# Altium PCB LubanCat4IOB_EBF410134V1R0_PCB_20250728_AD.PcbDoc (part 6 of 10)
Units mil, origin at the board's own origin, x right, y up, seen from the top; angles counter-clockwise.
Board outline 5236.21 x 4055.11 mil, 6 copper layers (TOP, GND02, ART03, PWR04, GND05, BOTTOM), stack 47.2 mil thick; 614 components, 490 nets, 2311 pads, 1916 vias.
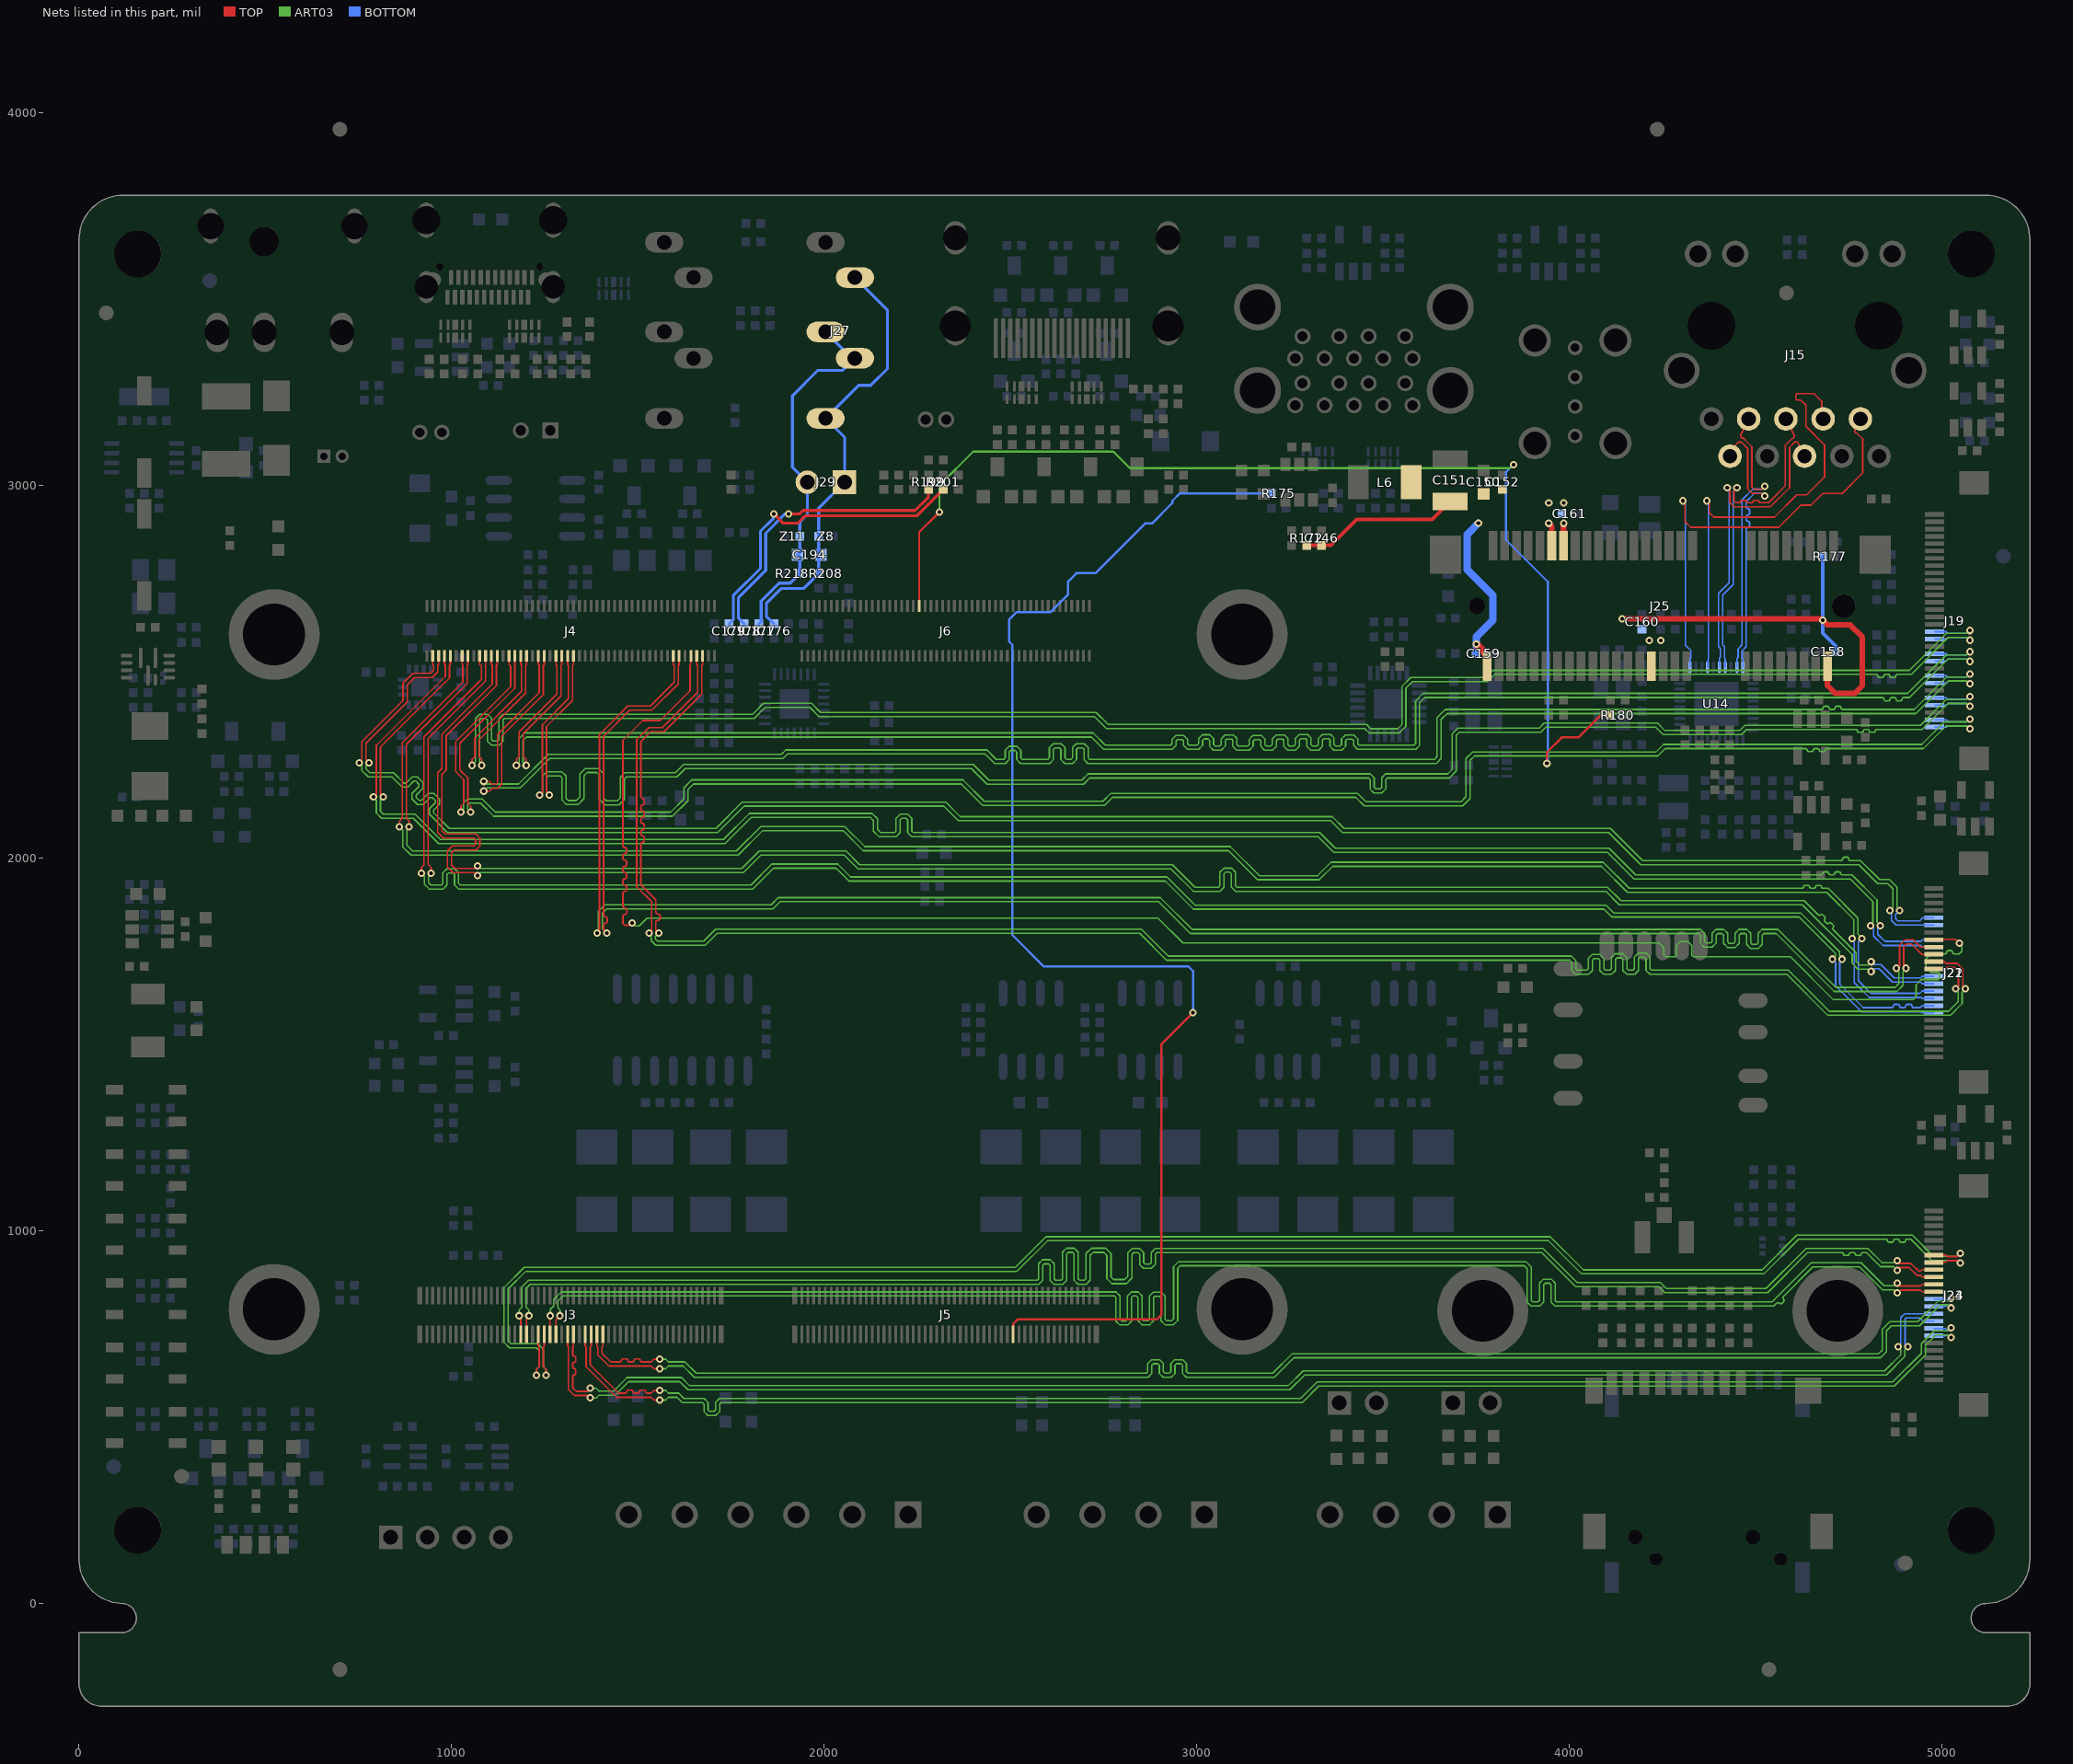
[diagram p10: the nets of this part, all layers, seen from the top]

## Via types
v1: diameter 20, hole 10, TOP to BOTTOM, 1912 vias
v2: diameter 40/50/50/50/50/40 (per signal layer), hole 0, TOP to BOTTOM, 4 vias

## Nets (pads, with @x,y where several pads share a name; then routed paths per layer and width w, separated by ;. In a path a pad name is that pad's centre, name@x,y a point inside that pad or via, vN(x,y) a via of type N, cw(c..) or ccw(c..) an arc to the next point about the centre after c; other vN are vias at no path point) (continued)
MDIN2_PHY: J15.6 U14.7 | length 907.5
  TOP w4.2: v1(4450,2994.37) 4441.85,2986.22 4441.85,2959.88 4447.56,2954.17 4456.77,2954.17 ccw(c4456.77,2956.61) 4459.2,2956.61 cw(c4463.36,2956.61) 4463.36,2960.77 4471.84,2960.77 cw(c4471.84,2956.61) 4476,2956.61 ccw(c4478.44,2956.61) 4478.44,2954.17 4490.36,2954.17 ccw(c4490.36,2956.61) 4492.8,2956.61 cw(c4496.74,2956.61) 4496.74,2960.55 4505.65,2960.55 cw(c4505.65,2956.61) 4509.6,2956.61 ccw(c4512.03,2956.61) 4512.03,2954.17 4534.8,2954.17 4580,2999.37 4580,3107.99 4597.73,3125.72 4602.08,3127.9 4604.09,3133.92 J15.6@4581.49,3179.13
  BOTTOM w4.2: U14.7@4418.62,2512.8 4418.62,2535.75 4416.47,2537.9 4416.47,2567.53 4411.86,2572.14 4411.86,2706.22 4440.2,2734.57 4440.2,2984.57 v1(4450,2994.37)
MDIN3_PHY: J15.9 U14.10 | length 769.7
  TOP w4.2: J15.9@4431.49,3079.13 4446.62,3109.39 4454.06,3116.83 4461.86,3116.83 4461.98,3116.77 4478.8,3099.95 4478.8,2992.21 4491.92,2979.09 4517.7,2979.09 v1(4524.52,2972.27)
  BOTTOM w4.2: U14.10@4465.87,2512.8 4465.87,2536 4464.18,2537.69 4464.18,2557.18 4475,2568 4475,2883.19 cw(c4479.5,2883.19) 4479.5,2887.69 ccw(c4479.5,2892.19) 4484,2892.19 4484,2899.99 ccw(c4479.5,2899.99) 4479.5,2904.49 cw(c4479.5,2908.99) 4475,2908.99 4475,2916.79 cw(c4479.5,2916.79) 4479.5,2921.29 ccw(c4479.5,2925.79) 4484,2925.79 4484,2933.59 ccw(c4479.5,2933.59) 4479.5,2938.09 cw(c4479.5,2942.59) 4475,2942.59 4475,2957.16 4497.41,2979.57 4516.39,2979.57 4523.69,2972.27 v1(4524.52,2972.27)
MDIP0_PHY: J15.2 U14.1 | length 1217
  TOP w4.2: v1(4304.5,2959.37) 4310.35,2953.52 4310.35,2903.71 4325.89,2888.17 4562.14,2888.17 4621.64,2947.67 4648.49,2947.67 4680.18,2979.36 4732.47,2979.36 4787.59,3034.48 4787.59,3125.41 4774.32,3138.68 4773.04,3139.97 4771.41,3140.78 4769.65,3141.66 4767.89,3142.54 4766.02,3148.17 J15.2@4781.49,3179.13
  BOTTOM w4.2: v1(4304.5,2959.37) 4305.04,2959.37 4311.9,2952.51 4311.9,2571.91 4326.33,2557.48 4326.33,2538.2 4324.13,2536 U14.1@4324.13,2512.8
MDIP1_PHY: J15.4 U14.4 | length 1230
  TOP w4.2: v1(4368.63,2959.37) 4376.17,2951.83 4376.17,2927.36 4387.96,2915.57 4550.79,2915.57 4610.29,2975.07 4637.14,2975.07 4685,3022.93 4685,3109.37 4635,3159.37 4635,3215.9 4620.94,3229.96 4610.9,3229.96 4607.93,3232.93 4607.93,3243.19 4612.13,3247.39 4656.7,3247.39 4677.64,3226.45 4677.64,3182.98 J15.4@4681.49,3179.13
  BOTTOM w4.2: v1(4368.63,2959.37) 4373.66,2954.34 4373.66,2954.24 4373.26,2953.84 4373.26,2531.39 4371.38,2529.52 U14.4@4371.38,2512.8
MDIP2_PHY: J15.5 U14.6 | length 905.6
  TOP w4.2: v1(4424,2994.37) 4430.65,2987.72 4430.65,2955.24 4442.93,2942.97 4539.44,2942.97 4591.2,2994.73 4591.2,3103.35 4604.36,3116.51 4608.05,3118.36 4612.64,3116.83 J15.5@4631.49,3079.13
  BOTTOM w4.2: U14.6@4402.87,2512.8 4402.87,2537.24 4405.27,2539.64 4405.27,2562.89 4400.66,2567.5 4400.66,2710.86 4429,2739.21 4429,2989.37 v1(4424,2994.37)
MDIP3_PHY: J15.8 U14.9 | length 772.6
  TOP w4.2: J15.8@4481.49,3179.13 4459.66,3135.47 4461.67,3129.45 4463.09,3128.03 4464.97,3128.03 4467.26,3126.66 4471.14,3124.72 4471.77,3122.82 4490,3104.59 4490,2996.85 4496.56,2990.29 4516.54,2990.29 v1(4524.52,2998.27)
  BOTTOM w4.2: U14.9@4450.12,2512.8 4450.12,2536 4452.98,2538.86 4452.98,2561.82 4463.8,2572.64 4463.8,2961.8 4492.77,2990.77 4517.02,2990.77 v1(4524.52,2998.27)
MIC1_L: C176.2 C194.1 J27.2 J27.4 J29.1 R208.2 Z8.2 | length 1210.5
  BOTTOM w8: C176.2@1865,2629.05 1845,2649.05 1845,2684.37 1885,2724.37 1945.32,2724.37 R208.2@1985.32,2764.37 1985.32,2808.19 C194.1@1991.5,2814.37 1985.32,2820.55 Z8.2@1985.32,2864.37 1985.32,2939.69 J29.1@2055,3009.37 2055,3129.35 J27.4@2003.77,3180.57 2092.57,3269.37 2125,3269.37 2170,3314.37 2170,3471.03 J27.2@2082.51,3558.52
MIC1_R: C177.2 C194.2 J27.3 J27.5 J29.2 R218.1 Z11.2 | length 1022.4
  BOTTOM w8: C177.2@1825,2629.05 1831,2635.05 1831,2690.17 1879.2,2738.37 1908.68,2738.37 R218.1@1934.68,2764.37 1934.68,2808.19 C194.2@1928.5,2814.37 1934.68,2820.55 Z11.2@1934.68,2864.37 1934.68,2903.05 1955,2923.37 J29.2@1955,3009.37 1915,3049.37 1915,3241.37 1983,3309.37 2049.89,3309.37 J27.3@2082.51,3341.99 2074.63,3341.99 J27.5@2003.77,3412.85
MIC2_L: C178.2 R199.2 | length 777.2
  TOP w8: v1(1904.37,2924.37) 1934.2,2924.37 1943.2,2933.37 2243.88,2933.37 2280,2969.49 R199.2@2280,2989.69
  BOTTOM w8: C178.2@1785,2629.05 1770,2644.05 1770,2699.57 1843,2772.57 1843,2872.37 1895,2924.37 v1(1904.37,2924.37)
MIC2_R: C179.2 R201.2 | length 847.8
  TOP w8: v1(1865,2924.37) 1890,2899.37 1929,2899.37 1949,2919.37 2249.68,2919.37 R201.2@2320,2989.69
  BOTTOM w8: C179.2@1745,2629.05 1756,2640.05 1756,2705.37 1829,2778.37 1829,2878.17 1865,2914.17 v1(1865,2924.37)
MINIPCIE_3V3: C146.1 C150.1 C151.1 C152.1 C158.1 C159.1 C160.1 C161.1 J25.2 J25.24 J25.39 J25.41 J25.52 L6.2 R172.1 R177.1 | length 2267.6
  TOP w10: R172.1@3295,2839.69 C146.1@3335,2839.69 3360.32,2839.69 3430,2909.37 3632.09,2909.37 C151.1@3680,2957.28
  TOP w15: v1(3945,2898.95) 3952.9,2891.05 J25.41@3952.9,2838.58 ; J25.39@3984.39,2838.58 3984.39,2898.34 v1(3985,2898.95) ; v1(4142,2642.37) 4677,2642.37 v1(4680,2639.37) 4693,2626.37 4754,2626.37 4787,2593.37 4787,2463.58 4765.79,2442.37 4714.27,2442.37 4693.06,2463.58 J25.2@4693.06,2515.74
  TOP w20: v1(3750,2574.37) 3779.67,2544.7 J25.52@3779.67,2515.74
  BOTTOM w10: v1(4680,2639.37) v1@4680.32,2639.69 ; R177.1@4680.32,2809.37 v1@4680.32,2639.69 ; C158.1@4714.68,2554.37 4714.68,2569.69 4680.32,2604.05 v1@4680.32,2639.69
  BOTTOM w20: v1(3750,2574.37) v1@3750.32,2574.05 ; C159.1@3750.32,2549.37 v1@3750.32,2574.05 ; v1(3756,2899.37) 3725.6,2868.97 3725.6,2774.57 3795,2705.17 3795,2639.37 3750.32,2594.69 v1@3750.32,2574.05
  other v1: 4246,2584.37 4215,2584.59 3945,2953.95 3985,2953.95
MINIPCIE_NWDISABLE: J6.42 R180.2 | length 3046
  TOP w6: J6.42@2255.11,2677.37 2255.11,2875.29 v1(2309.2,2929.37) ; v1(3940,2254.37) 3940,2284.37 3980,2324.37 4025,2324.37 4085,2384.37 R180.2@4110.32,2384.37
  ART03 w5.5: v1(2309.2,2929.37) 2309.2,3000.56 2400,3091.37 2776,3091.37 2820.6,3046.77 3840.4,3046.77 v1(3850,3056.37)
  BOTTOM w6: v1(3850,3056.37) 3830,3036.37 3830,2854.37 3942.4,2741.97 3942.4,2256.77 v1(3940,2254.37)
MINIPCIE_PWR_EN: J5.74 R175.1 | length 3637.6
  TOP w6: J5.74@2507.08,722.26 2507.08,750.37 2519.08,762.37 2893,762.37 2905,774.37 2905,1500.37 v1(2990,1585.37)
  BOTTOM w6: v1(2990,1585.37) 2990,1697.37 2978,1709.37 2590,1709.37 2505,1794.37 2505,2573 2496,2582 2496,2640 2516,2660 2607,2660 2655,2708 2655,2743 2677,2765 2728,2765 2862.37,2899.37 2881,2899.37 2935,2953.37 2935,2959.37 2955,2979.37 R175.1@3200.32,2979.37
MIPI_CSI0_RX_CLK0N: J3.52 J23.10 | length 3995.8
  TOP w4.2: J3.52@1327.26,722.26 1327.26,690.84 1324.98,688.57 1324.98,668 ccw(c1328.99,668) 1328.99,663.99 cw(c1328.99,659.98) 1333,659.98 1333,651.2 cw(c1328.99,651.2) 1328.99,647.19 ccw(c1328.99,643.18) 1324.98,643.18 1324.98,634.4 ccw(c1328.99,634.4) 1328.99,630.39 cw(c1328.99,626.38) 1333,626.38 1333,617.6 cw(c1328.99,617.6) 1328.99,613.59 ccw(c1328.99,609.58) 1324.98,609.58 1324.98,578.77 1334.38,569.37 1364.73,569.37 1372.53,577.17 v1(1372.53,577.77)
  ART03 w4: v1(1372.53,577.77) 1388.15,577.77 1395.65,570.27 1434.9,570.27 1471,606.37 1617,606.37 1639,584.37 3245.44,584.37 3285.44,624.37 4846.44,624.37 4890,667.93 4890,681.14 v1(4882.5,688.64)
  BOTTOM w4.2: v1(4882.5,688.64) 4889.9,696.04 4889.9,767.3 4900.16,777.56 J23.10@4978.61,777.56
MIPI_CSI0_RX_CLK0P: J3.50 J23.9 | length 3998
  TOP w4.2: J3.50@1311.51,722.26 1311.51,690.84 1313.78,688.57 1313.78,574.13 1329.74,558.17 1366.13,558.17 v1(1372.53,551.77)
  ART03 w4: v1(1372.53,551.77) 1388.15,551.77 1395.65,559.27 1439.46,559.27 1475.56,595.37 1612.44,595.37 1634.44,573.37 3250,573.37 3290,613.37 4851,613.37 4901,663.37 4901,681.14 v1(4908.5,688.64)
  BOTTOM w4.2: v1(4908.5,688.64) 4901.1,696.04 4901.1,762.66 4904.8,766.36 4941.01,766.36 4949.5,757.87 J23.9@4978.61,757.87
MIPI_CSI0_RX_CLK1N: J3.36 J24.10 | length 4582.1
  TOP w4.2: J3.36@1201.27,722.26 1201.27,766.23 v1(1207.4,772.36) ; v1(4880,894.37) 4887,901.37 4912.16,901.37 4932.82,880.71 4942.42,880.71 4947.15,875.98 J24.10@4978.61,875.98
  ART03 w4: v1(1207.4,772.36) 1207.4,787.99 1199.9,795.49 1199.9,845.27 1211.06,856.42 2576.02,856.42 2586.47,866.87 2586.47,907.37 2590.47,911.37 2602.47,911.37 2606.47,907.37 2606.47,866.87 2616.91,856.42 2640.56,856.42 2651,866.87 2651,938.37 2655,942.37 2667,942.37 2671,938.37 2671,866.87 2681.44,856.42 2703.05,856.42 2714,867.37 2714,934.37 2722,942.37 2751,942.37 2759,934.37 2759,871.81 2772.44,858.37 2811,858.37 2826.45,873.82 2826.45,936.81 2831,941.37 2842.72,941.37 2846.72,937.37 2846.72,909.81 2857.16,899.37 2878.28,899.37 2888.72,909.81 2888.72,937.37 2892.72,941.37 3925.84,941.37 4017.21,850 4240.44,850 4256.07,834.37 4532.56,834.37 4639.56,941.37 4732.28,941.37 cw(c4732.28,937.87) 4735.78,937.87 ccw(c4739.28,937.87) 4739.28,934.37 4748.28,934.37 ccw(c4748.28,937.87) 4751.78,937.87 cw(c4755.28,937.87) 4755.28,941.37 4764.28,941.37 cw(c4764.28,937.87) 4767.78,937.87 ccw(c4771.28,937.87) 4771.28,934.37 4780.28,934.37 ccw(c4780.28,937.87) 4783.78,937.87 cw(c4787.28,937.87) 4787.28,941.37 4797.44,941.37 4834.94,903.87 4870.5,903.87 v1(4880,894.37)
MIPI_CSI0_RX_CLK1P: J3.34 J24.9 | length 4581.8
  TOP w4.2: v1(1181.4,772.36) 1185.52,768.23 J3.34@1185.52,722.26 ; v1(4880,920.37) 4887.8,912.57 4916.8,912.57 4937.46,891.91 4943.4,891.91 4947.15,895.67 J24.9@4978.61,895.67
  ART03 w4: v1(1181.4,772.36) 1181.4,787.99 1188.9,795.49 1188.9,849.83 1206.5,867.42 2571.47,867.42 2575.47,871.42 2575.47,911.93 2585.91,922.37 2607.02,922.37 2617.47,911.93 2617.47,871.42 2621.47,867.42 2636,867.42 2640,871.42 2640,942.93 2650.44,953.37 2671.56,953.37 2682,942.93 2682,871.42 2686,867.42 2698.5,867.42 2703,871.93 2703,938.93 2717.44,953.37 2755.56,953.37 2770,938.93 2770,876.37 2777,869.37 2806.44,869.37 2815.45,878.37 2815.45,941.37 2826.44,952.37 2847.28,952.37 2857.72,941.93 2857.72,914.37 2861.72,910.37 2873.72,910.37 2877.72,914.37 2877.72,941.93 2888.16,952.37 3930.4,952.37 4021.77,861 4245,861 4260.63,845.37 4528,845.37 4635,952.37 4802,952.37 4839.5,914.87 4874.5,914.87 v1(4880,920.37)
MIPI_CSI0_RX_D0N: J3.62 J23.12 | length 3998.5
  TOP w4.2: J3.62@1406,722.26 1406,690.84 1403.72,688.57 1403.72,671.49 1426.84,648.37 1452.07,648.37 ccw(c1452.07,652.37) 1456.07,652.37 cw(c1460.07,652.37) 1460.07,656.37 1468.87,656.37 cw(c1468.87,652.37) 1472.87,652.37 ccw(c1476.87,652.37) 1476.87,648.37 1485.67,648.37 ccw(c1485.67,652.37) 1489.67,652.37 cw(c1493.67,652.37) 1493.67,656.37 1502.47,656.37 cw(c1502.47,652.37) 1506.47,652.37 ccw(c1510.47,652.37) 1510.47,648.37 1535.95,648.37 1543.35,655.77 v1(1559,655.77)
  ART03 w4: v1(1559,655.77) 1574.63,655.77 1582.13,648.27 1626.1,648.27 1656.55,617.82 2864.61,617.82 2868.61,621.82 2868.61,643.93 2879.05,654.37 2900.17,654.37 2910.61,643.93 2910.61,621.82 2914.61,617.82 2926.61,617.82 2930.61,621.82 2930.61,643.93 2941.05,654.37 2962.17,654.37 2972.61,643.93 2972.61,621.82 2976.61,617.82 3203.89,617.82 3256.44,670.37 4830.44,670.37 4840,679.93 4840,735.93 4860.44,756.37 4935.44,756.37 4991.44,812.37 5018,812.37 v1(5025,819.37)
  BOTTOM w4.2: J23.12@4978.61,816.93 5010.03,816.93 5013.47,813.49 5019.12,813.49 v1(5025,819.37)
MIPI_CSI0_RX_D0P: J3.60 J23.11 | length 3999.2
  TOP w4.2: J3.60@1390.25,722.26 1390.25,690.84 1392.52,688.57 1392.52,666.85 1422.2,637.17 1535.95,637.17 1543.35,629.77 v1(1559,629.77)
  ART03 w4: v1(1559,629.77) 1574.63,629.77 1582.13,637.27 1621.54,637.27 1651.99,606.82 2869.17,606.82 2879.61,617.26 2879.61,639.37 2883.61,643.37 2895.61,643.37 2899.61,639.37 2899.61,617.26 2910.05,606.82 2931.17,606.82 2941.61,617.26 2941.61,639.37 2945.61,643.37 2957.61,643.37 2961.61,639.37 2961.61,617.26 2972.05,606.82 3208.45,606.82 3261,659.37 4835,659.37 4851,675.37 4851,731.37 4865,745.37 4940,745.37 4996,801.37 5017,801.37 v1(5025,793.37)
  BOTTOM w4.2: J23.11@4978.61,797.24 5010.03,797.24 5012.75,799.96 5018.41,799.96 v1(5025,793.37)
MIPI_CSI0_RX_D1N: J3.58 J23.8 | length 3994.3
  TOP w4.2: J3.58@1374.5,722.26 1374.5,690.84 1372.23,688.57 1372.23,640.14 1448,564.37 1466.3,564.37 ccw(c1466.3,568.37) 1470.3,568.37 cw(c1474.3,568.37) 1474.3,572.37 1483.1,572.37 cw(c1483.1,568.37) 1487.1,568.37 ccw(c1491.1,568.37) 1491.1,564.37 1499.9,564.37 ccw(c1499.9,568.37) 1503.9,568.37 cw(c1507.9,568.37) 1507.9,572.37 1516.7,572.37 cw(c1516.7,568.37) 1520.7,568.37 ccw(c1524.7,568.37) 1524.7,564.37 1535.95,564.37 1543.35,571.77 v1(1559,571.77)
  ART03 w4: v1(1559,571.77) 1574.63,571.77 1582.13,564.27 1609.66,564.27 1623.56,550.37 1677.87,550.37 1688.31,539.93 1688.31,519.37 1692.31,515.37 1704.31,515.37 1708.31,519.37 1708.31,539.93 1718.75,550.37 3279,550.37 3323,594.37 4868,594.37 4945,671.37 4945,697.37 4979.5,731.87 5017.5,731.87 v1(5025,739.37)
  BOTTOM w4.2: J23.8@4978.61,738.19 5010.03,738.19 5014.1,734.12 5019.75,734.12 v1(5025,739.37)
MIPI_CSI0_RX_D1P: J3.56 J23.7 | length 3994.5
  TOP w4.2: J3.56@1358.75,722.26 1358.75,690.84 1361.03,688.57 1361.03,635.5 1443.36,553.17 1535.95,553.17 1543.35,545.77 v1(1559,545.77)
  ART03 w4: v1(1559,545.77) 1574.63,545.77 1582.13,553.27 1605.1,553.27 1619,539.37 1673.31,539.37 1677.31,535.37 1677.31,514.81 1687.75,504.37 1708.87,504.37 1719.31,514.81 1719.31,535.37 1723.31,539.37 3283.56,539.37 3327.56,583.37 4872.56,583.37 4956,666.81 4956,692.81 4984.06,720.87 5017.5,720.87 v1(5025,713.37)
  BOTTOM w4.2: J23.7@4978.61,718.5 5010.03,718.5 5012.12,720.59 5017.78,720.59 v1(5025,713.37)
MIPI_CSI0_RX_D2N: J3.46 J24.12 | length 4577.4
  TOP w4.2: J3.46@1280.01,722.26 1280.01,761.23 v1(1291.14,772.36) ; v1(4880,833.37) 4882.01,833.37 4889.5,840.86 4942.91,840.86 4947.15,836.61 J24.12@4978.61,836.61
  ART03 w4: v1(1291.14,772.36) 1291.14,787.99 1285,794.12 1285,811.37 1298.8,825.17 2779.24,825.17 2783.24,821.17 2783.24,757.81 2793.69,747.37 2814.8,747.37 2825.24,757.81 2825.24,821.17 2829.24,825.17 2838.24,825.17 2842.24,821.17 2842.24,758.61 2852.69,748.17 2873.8,748.17 2884.24,758.61 2884.24,820.37 2888.24,824.37 2900.24,824.37 2904.24,820.37 2904.24,758.61 2914.69,748.17 2937.56,748.17 2949,759.61 2949,899.37 2956,906.37 3879.2,906.37 3887.2,898.37 3887.2,808.81 3897.64,798.37 3920.63,798.37 3931.07,808.81 3931.07,855.37 3935.07,859.37 3947.07,859.37 3951.07,855.37 3951.07,808.81 3961.51,798.37 4549,798.37 4556.27,805.64 cw(c4560.02,801.89) 4563.77,805.64 ccw(c4567.52,809.39) 4571.27,805.64 4575.09,809.46 ccw(c4571.34,813.21) 4575.09,816.96 cw(c4578.84,820.71) 4575.09,824.45 4654,903.37 4778.84,903.37 4840.84,841.37 4872,841.37 v1(4880,833.37)
MIPI_CSI0_RX_D2P: J3.44 J24.11 | length 4579.9
  TOP w4.2: J3.44@1264.26,722.26 1264.26,771.48 v1(1265.14,772.36) ; v1(4880,859.37) 4887.31,852.05 4942.91,852.05 4947.15,856.3 J24.11@4978.61,856.3
  ART03 w4: v1(1265.14,772.36) 1265.14,789.51 1274,798.37 1274,815.93 1294.24,836.17 2783.8,836.17 2794.24,825.73 2794.24,762.37 2798.24,758.37 2810.24,758.37 2814.24,762.37 2814.24,825.73 2824.69,836.17 2842.8,836.17 2853.24,825.73 2853.24,763.17 2857.24,759.17 2869.24,759.17 2873.24,763.17 2873.24,824.93 2883.69,835.37 2904.8,835.37 2915.24,824.93 2915.24,763.17 2919.24,759.17 2933,759.17 2938,764.17 2938,903.93 2951.44,917.37 3883.76,917.37 3898.2,902.93 3898.2,813.37 3902.2,809.37 3916.07,809.37 3920.07,813.37 3920.07,859.93 3930.51,870.37 3951.63,870.37 3962.07,859.93 3962.07,813.37 3966.07,809.37 4544.44,809.37 4649.44,914.37 4783.4,914.37 4845.4,852.37 4873,852.37 v1(4880,859.37)
MIPI_CSI0_RX_D3N: J3.42 J24.8 | length 4578
  TOP w4.2: J3.42@1248.52,722.26 1248.52,690.84 1246.24,688.57 1246.24,635.17 1253.64,627.77 v1(1253.64,612.12) ; J24.8@4978.61,915.35 5010.07,915.35 5014.81,920.1 5043.27,920.1 v1(5050,913.37)
  ART03 w4: v1(1253.64,612.12) 1253.64,627.75 1246.14,635.25 1246.14,682.53 1231.7,696.97 1160,696.97 1152,704.97 1152,844.01 1199.41,891.42 2517.61,891.42 2599.56,973.37 3944.4,973.37 4033.4,884.37 4522.4,884.37 4615.4,977.37 4850.21,977.37 cw(c4850.21,973.37) 4854.21,973.37 ccw(c4858.21,973.37) 4858.21,969.37 4866.21,969.37 ccw(c4866.21,973.37) 4870.21,973.37 cw(c4874.21,973.37) 4874.21,977.37 4882.21,977.37 cw(c4882.21,973.37) 4886.21,973.37 ccw(c4890.21,973.37) 4890.21,969.37 4898.21,969.37 ccw(c4898.21,973.37) 4902.21,973.37 cw(c4906.21,973.37) 4906.21,977.37 4916.44,977.37 4972.94,920.87 5042.5,920.87 v1(5050,913.37)
MIPI_CSI0_RX_D3P: J3.40 J24.7 | length 4578.1
  TOP w4.2: v1(1227.64,612.12) 1227.64,627.77 1235.04,635.17 1235.04,688.57 1232.77,690.84 J3.40@1232.77,722.26 ; J24.7@4978.61,935.04 5010.07,935.04 5013.81,931.29 5041.93,931.29 v1(5050,939.37)
  ART03 w4: v1(1227.64,612.12) 1227.64,627.75 1235.14,635.25 1235.14,677.97 1227.14,685.97 1155.44,685.97 1141,700.41 1141,848.57 1194.85,902.42 2513.06,902.42 2595,984.37 3948.96,984.37 4037.96,895.37 4517.84,895.37 4610.84,988.37 4921,988.37 4977.5,931.87 5042.5,931.87 v1(5050,939.37)
MIPI_DPHY0_RX_CLKN: J4.15 J21.10 | length 5055.1
  TOP w4.2: v1(886,2084.37) 886,2100.02 878.6,2107.42 878.6,2305.73 1041.51,2468.64 1041.51,2517.7 1043.79,2519.97 J4.15@1043.79,2543.51
  ART03 w4: v1(886,2084.37) 880,2078.37 880,2034.93 895.56,2019.37 1764.44,2019.37 1830.44,2085.37 2055.2,2085.37 2109.2,2031.37 3090,2031.37 3168,1953.37 3324.44,1953.37 3360.44,1989.37 4091,1989.37 4161,1919.37 4625.3,1919.37 ccw(c4625.3,1923.07) 4629,1923.07 cw(c4632.7,1923.07) 4632.7,1926.77 4641.3,1926.77 cw(c4641.3,1923.07) 4645,1923.07 ccw(c4648.7,1923.07) 4648.7,1919.37 4657.3,1919.37 ccw(c4657.3,1923.07) 4661,1923.07 cw(c4664.7,1923.07) 4664.7,1926.77 4673.3,1926.77 cw(c4673.3,1923.07) 4677,1923.07 ccw(c4680.7,1923.07) 4680.7,1919.37 4695,1919.37 4775,1839.37 4775,1796.66 4779,1792.66 4779,1790.37 v1(4785,1784.37)
  BOTTOM w4.2: v1(4785,1784.37) 4776.1,1775.47 4776.1,1671.11 4809.76,1637.45 4940.95,1637.45 4947.19,1643.7 J21.10@4978.61,1643.7
MIPI_DPHY0_RX_CLKP: J4.13 J21.9 | length 5053
  TOP w4.2: v1(860,2084.37) 860,2100.02 867.4,2107.42 867.4,2310.37 1030.31,2473.28 1030.31,2517.7 1028.04,2519.97 J4.13@1028.04,2543.51
  ART03 w4: v1(860,2084.37) 869,2075.37 869,2030.37 891,2008.37 1769,2008.37 1835,2074.37 2050.64,2074.37 2104.64,2020.37 3085.44,2020.37 3163.44,1942.37 3329,1942.37 3365,1978.37 4086.44,1978.37 4156.44,1908.37 4690.44,1908.37 4764,1834.81 4764,1789.37 v1(4759,1784.37)
  BOTTOM w4.2: v1(4759,1784.37) 4764.9,1778.47 4764.9,1666.47 4805.12,1626.25 4944.95,1626.25 4947.19,1624.01 J21.9@4978.61,1624.01
MIPI_DPHY0_RX_D0N: J4.25 J21.12 | length 5055.1
  TOP w4.2: v1(1070,1979.47) 1063.4,1972.87 1008.4,1972.87 1000,1981.27 1000,2014.93 1007.16,2022.09 1065.04,2022.09 1075.8,2032.85 1075.8,2054.73 1065.04,2065.49 982.4,2065.49 974,2073.89 974,2224.93 985.4,2236.33 985.4,2327.97 1120.25,2462.82 1120.25,2517.7 1122.53,2519.97 J4.25@1122.53,2543.51
  ART03 w4: v1(1070,1979.47) 1077.1,1972.37 1778.84,1972.37 1825.84,2019.37 2058.56,2019.37 2095.36,1982.57 2935.16,1982.57 2995.36,1922.37 3058.36,1922.37 3062.36,1926.37 3062.36,1962.93 3072.8,1973.37 3093.91,1973.37 3104.36,1962.93 3104.36,1926.37 3108.36,1922.37 4102.56,1922.37 4138.56,1886.37 4630.19,1886.37 4668.34,1848.22 ccw(c4671.34,1851.22) 4674.34,1848.22 cw(c4677.35,1845.21) 4680.35,1848.22 4685.66,1842.91 cw(c4682.65,1839.91) 4685.66,1836.9 ccw(c4688.66,1833.9) 4685.66,1830.9 4690.97,1825.59 ccw(c4693.97,1828.59) 4696.97,1825.59 cw(c4699.98,1822.59) 4702.98,1825.59 4708.29,1820.28 cw(c4705.28,1817.28) 4708.29,1814.28 ccw(c4711.29,1811.27) 4708.29,1808.27 4770.17,1746.38 4770.17,1722.62 4779.17,1713.62 4801.95,1713.62 v1(4810.45,1722.12)
  BOTTOM w4.2: v1(4810.45,1722.12) 4817.85,1714.72 4836.21,1714.72 4872.1,1678.82 4942.95,1678.82 4947.19,1683.07 J21.12@4978.61,1683.07
MIPI_DPHY0_RX_D0P: J4.23 J21.11 | length 5055
  TOP w4.2: v1(1070,1953.47) 1070,1953.87 1062.2,1961.67 1003.76,1961.67 988.8,1976.63 988.8,2019.57 1002.52,2033.29 1060.4,2033.29 1064.6,2037.49 1064.6,2050.09 1060.4,2054.29 977.76,2054.29 962.8,2069.25 962.8,2229.57 974.2,2240.97 974.2,2332.61 1109.05,2467.46 1109.05,2517.7 1106.78,2519.97 J4.23@1106.78,2543.51
  ART03 w4: v1(1070,1953.47) 1070,1954.01 1077.36,1961.37 1783.4,1961.37 1830.4,2008.37 2054,2008.37 2090.8,1971.57 2930.6,1971.57 2990.8,1911.37 3062.91,1911.37 3073.36,1921.81 3073.36,1958.37 3077.36,1962.37 3089.36,1962.37 3093.36,1958.37 3093.36,1921.81 3103.8,1911.37 4098,1911.37 4134,1875.37 4625.63,1875.37 4759.17,1741.83 4759.17,1718.06 4774.61,1702.62 4803.95,1702.62 v1(4810.45,1696.12)
  BOTTOM w4.2: v1(4810.45,1696.12) 4817.85,1703.52 4831.48,1703.52 4867.38,1667.62 4942.95,1667.62 4947.19,1663.38 J21.11@4978.61,1663.38
MIPI_DPHY0_RX_D1N: J4.21 J21.8 | length 5052.4
  TOP w4.2: v1(945,1959.37) 945,1975.02 936.9,1983.12 936.9,2321.67 1091.03,2475.8 J4.21@1091.03,2543.51
  ART03 w4: v1(945,1959.37) 938,1952.37 938,1934.93 944.36,1928.57 972.8,1928.57 976.8,1932.57 976.8,1961.33 987.24,1971.77 1008.36,1971.77 1018.8,1961.33 1018.8,1932.57 1022.8,1928.57 1803.84,1928.57 1859.64,1984.37 2036.56,1984.37 2071.16,1949.77 2920.16,1949.77 2995.56,1874.37 4098,1874.37 4119,1853.37 4621,1853.37 4725,1749.37 4725,1736.87 v1(4732.5,1729.37)
  BOTTOM w4.2: v1(4732.5,1729.37) 4726.1,1722.97 4726.1,1662.11 4789.13,1599.08 4865.23,1599.08 ccw(c4865.23,1603.54) 4869.69,1603.54 cw(c4874.15,1603.54) 4874.15,1608 4882.03,1608 cw(c4882.03,1603.54) 4886.49,1603.54 ccw(c4890.95,1603.54) 4890.95,1599.08 4898.84,1599.08 ccw(c4898.84,1603.54) 4903.29,1603.54 cw(c4907.75,1603.54) 4907.75,1608 4915.64,1608 cw(c4915.64,1603.54) 4920.09,1603.54 ccw(c4924.55,1603.54) 4924.55,1599.08 4942.71,1599.08 4947.96,1604.33 J21.8@4978.61,1604.33
MIPI_DPHY0_RX_D1P: J4.19 J21.7 | length 5052.3
  TOP w4.2: v1(919,1959.37) 919,1975.02 925.7,1981.72 925.7,2326.31 1079.83,2480.44 1079.83,2515.42 1075.28,2519.97 J4.19@1075.28,2543.51
  ART03 w4: v1(919,1959.37) 927,1951.37 927,1930.37 939.8,1917.57 977.36,1917.57 987.8,1928.01 987.8,1956.77 991.8,1960.77 1003.8,1960.77 1007.8,1956.77 1007.8,1928.01 1018.24,1917.57 1808.4,1917.57 1864.2,1973.37 2032,1973.37 2066.6,1938.77 2915.6,1938.77 2991,1863.37 4093.44,1863.37 4114.44,1842.37 4616.44,1842.37 4714,1744.81 4714,1736.87 v1(4706.5,1729.37)
  BOTTOM w4.2: v1(4706.5,1729.37) 4714.9,1720.97 4714.9,1657.47 4784.49,1587.88 4943.95,1587.88 4947.19,1584.64 J21.7@4978.61,1584.64
MIPI_DPHY0_RX_D2N: J4.9 J21.17 | length 5048.9
  TOP w4.2: v1(816,2164.37) 809.1,2171.27 809.1,2298.47 994.27,2483.64 994.27,2517.7 996.54,2519.97 J4.9@996.54,2543.51
  ART03 w4: v1(816,2164.37) 809,2157.37 809,2126.17 817,2118.17 901.76,2118.17 969.56,2050.37 1729.4,2050.37 1799.4,2120.37 2128.76,2120.37 2143.2,2105.93 2143.2,2077.37 2151.2,2069.37 2189.17,2069.37 2193.17,2073.37 2193.17,2107.53 2203.61,2117.97 2224.72,2117.97 2235.17,2107.53 2235.17,2073.37 2239.17,2069.37 3329.8,2069.37 3371.8,2027.37 4106.56,2027.37 4178.56,1955.37 4676.29,1955.37 ccw(c4676.29,1959.47) 4680.39,1959.47 cw(c4684.49,1959.47) 4684.49,1963.57 4692.29,1963.57 cw(c4692.29,1959.47) 4696.39,1959.47 ccw(c4700.49,1959.47) 4700.49,1955.37 4708.29,1955.37 ccw(c4708.29,1959.47) 4712.39,1959.47 cw(c4716.49,1959.47) 4716.49,1963.57 4724.29,1963.57 cw(c4724.29,1959.47) 4728.39,1959.47 ccw(c4732.49,1959.47) 4732.49,1955.37 4759,1955.37 4826,1888.37 4826,1828.37 v1(4835,1819.37)
  BOTTOM w4.2: v1(4835,1819.37) 4828.1,1812.47 4828.1,1796.27 4847.3,1777.07 4943.7,1777.07 4948.12,1781.49 J21.17@4978.61,1781.49
MIPI_DPHY0_RX_D2P: J4.7 J21.16 | length 5048.9
  TOP w4.2: v1(790,2164.37) 797.9,2172.27 797.9,2303.11 983.07,2488.28 983.07,2517.7 980.79,2519.97 J4.7@980.79,2543.51
  ART03 w4: v1(790,2164.37) 798,2156.37 798,2121.61 812.44,2107.17 897.2,2107.17 965,2039.37 1733.96,2039.37 1803.96,2109.37 2124.2,2109.37 2132.2,2101.37 2132.2,2072.81 2146.64,2058.37 2193.72,2058.37 2204.17,2068.81 2204.17,2102.97 2208.17,2106.97 2220.17,2106.97 2224.17,2102.97 2224.17,2068.81 2234.61,2058.37 3325.24,2058.37 3367.24,2016.37 4102,2016.37 4174,1944.37 4754.44,1944.37 4815,1883.82 4815,1825.37 v1(4809,1819.37)
  BOTTOM w4.2: v1(4809,1819.37) 4816.9,1811.47 4816.9,1791.1 4842.13,1765.87 4943.7,1765.87 4947.76,1761.81 J21.16@4978.61,1761.81
MIPI_DPHY0_RX_D3N: J4.5 J21.20 | length 5052.3
  TOP w4.2: v1(778,2256.37) 770,2264.37 770,2308.37 881,2419.37 881,2465.33 900.84,2485.17 947.81,2485.17 962.77,2500.13 962.77,2517.7 965.05,2519.97 J4.5@965.05,2543.51
  ART03 w4: v1(778,2256.37) 770,2248.37 770,2239.93 780.56,2229.37 844.56,2229.37 872.05,2201.88 877.7,2201.88 893.81,2217.99 908.58,2217.99 923.52,2203.05 923.52,2188.29 904.61,2169.38 904.61,2163.72 912.69,2155.63 919.15,2155.63 937.66,2174.14 952.43,2174.14 967.36,2159.21 967.36,2144.44 951.25,2128.33 951.25,2122.67 993.56,2080.37 1709.84,2080.37 1780.44,2150.97 2325.96,2150.97 2365.16,2111.77 3364.16,2111.77 3395.56,2080.37 4110.2,2080.37 4196.8,1993.77 4729.27,1993.77 ccw(c4729.27,1998.37) 4733.87,1998.37 cw(c4738.47,1998.37) 4738.47,2002.97 4745.27,2002.97 cw(c4745.27,1998.37) 4749.87,1998.37 ccw(c4754.47,1998.37) 4754.47,1993.77 4781.56,1993.77 4832.56,1942.77 4859.2,1942.77 4879.37,1922.6 4879.37,1866.87 v1(4886.87,1859.37)
  BOTTOM w4.2: v1(4886.87,1859.37) 4886.33,1859.37 4875.97,1849.01 4875.97,1837.76 4881.67,1832.06 4940.69,1832.06 4949.18,1840.55 J21.20@4978.61,1840.55
MIPI_DPHY0_RX_D3P: J4.3 J21.19 | length 5052.9
  TOP w4.2: v1(752,2256.37) 752.4,2256.37 758.8,2262.77 758.8,2313.01 869.8,2424.01 869.8,2469.97 896.2,2496.37 943.17,2496.37 951.57,2504.77 951.57,2517.7 949.3,2519.97 J4.3@949.3,2543.51
  ART03 w4: v1(752,2256.37) 759,2249.37 759,2235.37 776,2218.37 840,2218.37 867.49,2190.88 882.26,2190.88 898.37,2206.99 904.02,2206.99 912.52,2198.5 912.52,2192.84 893.61,2173.93 893.61,2159.16 908.14,2144.63 923.71,2144.63 942.22,2163.14 947.87,2163.14 956.36,2154.65 956.36,2149 940.25,2132.89 940.25,2118.12 989,2069.37 1714.4,2069.37 1785,2139.97 2321.4,2139.97 2360.6,2100.77 3359.6,2100.77 3391,2069.37 4105.64,2069.37 4192.24,1982.77 4777,1982.77 4828,1931.77 4854.64,1931.77 4868.37,1918.04 4868.37,1866.87 v1(4860.87,1859.37)
  BOTTOM w4.2: v1(4860.87,1859.37) 4864.77,1855.47 4864.77,1833.12 4877.03,1820.86 J21.19@4978.61,1820.86
MIPI_DPHY0_TX_CLKN: J4.41 J19.24 | length 4930.8
  TOP w4.2: v1(1086.23,2180.21) 1101.88,2180.21 1109.28,2187.61 1123.44,2187.61 1134.2,2198.37 1134.2,2327.73 1246.24,2439.77 1246.24,2517.7 1248.51,2519.97 J4.41@1248.51,2543.51
  ART03 w4: v1(1086.23,2180.21) 1094.4,2188.37 1184,2188.37 1263.6,2267.97 1889.76,2267.97 1901.56,2279.77 2432.4,2279.77 2457.6,2254.57 2486.39,2254.57 2496.83,2265.01 2496.83,2285.57 2500.83,2289.57 2512.83,2289.57 2516.83,2285.57 2516.83,2265.01 2527.28,2254.57 2604.97,2254.57 2615.42,2265.01 2615.42,2292.57 2619.42,2296.57 2631.42,2296.57 2635.42,2292.57 2635.42,2265.01 2645.86,2254.57 2666.97,2254.57 2677.42,2265.01 2677.42,2292.57 2681.42,2296.57 2693.42,2296.57 2697.42,2292.57 2697.42,2265.01 2707.86,2254.57 3642.8,2254.57 3656.2,2267.97 3656.2,2372.57 3672,2388.37 4930.4,2388.37 5017.9,2475.87 5067.5,2475.87 v1(5075,2468.37)
  BOTTOM w4.2: J19.24@4980.62,2470.25 5012.04,2470.25 5016.78,2474.99 5068.38,2474.99 v1(5075,2468.37)
MIPI_DPHY0_TX_CLKP: J4.39 J19.23 | length 4931.6
  TOP w4.2: v1(1086.23,2206.21) 1101.88,2206.21 1109.28,2198.81 1118.8,2198.81 1123,2203.01 1123,2332.37 1235.04,2444.41 1235.04,2517.7 1232.76,2519.97 J4.39@1232.76,2543.51
  ART03 w4: v1(1086.23,2206.21) 1093.07,2199.37 1179.44,2199.37 1259.04,2278.97 1885.2,2278.97 1897,2290.77 2436.96,2290.77 2462.16,2265.57 2481.83,2265.57 2485.83,2269.57 2485.83,2290.13 2496.28,2300.57 2517.39,2300.57 2527.83,2290.13 2527.83,2269.57 2531.83,2265.57 2600.42,2265.57 2604.42,2269.57 2604.42,2297.13 2614.86,2307.57 2635.97,2307.57 2646.42,2297.13 2646.42,2269.57 2650.42,2265.57 2662.42,2265.57 2666.42,2269.57 2666.42,2297.13 2676.86,2307.57 2697.97,2307.57 2708.42,2297.13 2708.42,2269.57 2712.42,2265.57 3638.24,2265.57 3645.2,2272.53 3645.2,2377.13 3667.44,2399.37 4677.12,2399.37 ccw(c4677.12,2403.67) 4681.42,2403.67 cw(c4685.72,2403.67) 4685.72,2407.97 4693.12,2407.97 cw(c4693.12,2403.67) 4697.42,2403.67 ccw(c4701.72,2403.67) 4701.72,2399.37 4709.12,2399.37 ccw(c4709.12,2403.67) 4713.42,2403.67 cw(c4717.72,2403.67) 4717.72,2407.97 4725.12,2407.97 cw(c4725.12,2403.67) 4729.42,2403.67 ccw(c4733.72,2403.67) 4733.72,2399.37 4925.84,2399.37 5013.34,2486.87 5067.5,2486.87 v1(5075,2494.37)
  BOTTOM w4.2: J19.23@4980.62,2489.94 5012.04,2489.94 5015.78,2486.19 5066.82,2486.19 v1(5075,2494.37)
MIPI_DPHY0_TX_D0N: J4.51 J19.27 | length 4928.2
  TOP w4.2: v1(1262.4,2169.37) 1255,2176.77 1255,2353.57 1324.98,2423.55 1324.98,2517.7 1327.25,2519.97 J4.51@1327.25,2543.51
  ART03 w4: v1(1262.4,2169.37) 1255.4,2176.37 1255.4,2216.87 1259.9,2221.37 1291.24,2221.37 1296.6,2216.01 1296.6,2156.01 1308.69,2143.93 1339.16,2143.93 1355.4,2160.17 1355.4,2221.77 1363.67,2230.04 1389.33,2230.04 1396.8,2222.57 1396.8,2157.81 1411.24,2143.37 1449.36,2143.37 1463.8,2157.81 1463.8,2212.97 1469,2218.17 1604.6,2218.17 1627.4,2240.97 2395.4,2240.97 2437.4,2198.97 2696.2,2198.97 2712.6,2215.37 3461.43,2215.37 3465.43,2211.37 3465.43,2185.61 3475.87,2175.17 3496.99,2175.17 3507.43,2185.61 3507.43,2211.37 3511.43,2215.37 3678.2,2215.37 3697,2234.17 3697,2329.97 3705,2337.97 3923.4,2337.97 3937,2351.57 4232.2,2351.57 4252,2331.77 4462,2331.77 4476,2345.77 4769.13,2345.77 cw(c4769.13,2341.77) 4773.13,2341.77 ccw(c4777.13,2341.77) 4777.13,2337.77 4785.13,2337.77 ccw(c4785.13,2341.77) 4789.13,2341.77 cw(c4793.13,2341.77) 4793.13,2345.77 4801.13,2345.77 cw(c4801.13,2341.77) 4805.13,2341.77 ccw(c4809.13,2341.77) 4809.13,2337.77 4817.13,2337.77 ccw(c4817.13,2341.77) 4821.13,2341.77 cw(c4825.13,2341.77) 4825.13,2345.77 4946.96,2345.77 5016.56,2415.37 5067.5,2415.37 v1(5075,2407.87)
  BOTTOM w4.2: J19.27@4980.62,2411.2 5012.04,2411.2 5016.28,2415.44 5067.43,2415.44 v1(5075,2407.87)
MIPI_DPHY0_TX_D0P: J4.49 J19.26 | length 4928.5
  TOP w4.2: v1(1236.4,2169.37) 1243.8,2176.77 1243.8,2358.21 1313.78,2428.19 1313.78,2517.7 1311.5,2519.97 J4.49@1311.5,2543.51
  ART03 w4: v1(1236.4,2169.37) 1244.4,2177.37 1244.4,2221.43 1255.34,2232.37 1295.8,2232.37 1307.6,2220.57 1307.6,2160.57 1313.24,2154.93 1334.6,2154.93 1344.4,2164.73 1344.4,2226.33 1359.11,2241.04 1393.89,2241.04 1407.8,2227.13 1407.8,2162.37 1415.8,2154.37 1444.8,2154.37 1452.8,2162.37 1452.8,2217.53 1464.44,2229.17 1600.04,2229.17 1622.84,2251.97 2399.96,2251.97 2441.96,2209.97 2691.64,2209.97 2708.04,2226.37 3465.99,2226.37 3476.43,2215.93 3476.43,2190.17 3480.43,2186.17 3492.43,2186.17 3496.43,2190.17 3496.43,2215.93 3506.87,2226.37 3673.64,2226.37 3686,2238.73 3686,2334.53 3700.44,2348.97 3918.84,2348.97 3932.44,2362.57 4236.76,2362.57 4256.56,2342.77 4457.44,2342.77 4471.44,2356.77 4942.4,2356.77 5012,2426.37 5067.5,2426.37 v1(5075,2433.87)
  BOTTOM w4.2: J19.26@4980.62,2430.88 5012.04,2430.88 5016.28,2426.64 5067.77,2426.64 v1(5075,2433.87)
MIPI_DPHY0_TX_D1N: J4.47 J19.21 | length 4933
  TOP w4.2: v1(1200,2249.37) 1200,2265.02 1192.6,2272.42 1192.6,2334.77 1293.48,2435.65 1293.48,2517.7 1295.76,2519.97 J4.47@1295.76,2543.51
  ART03 w4: v1(1200,2249.37) 1192,2257.37 1192,2316.37 1201,2325.37 2717.24,2325.37 2750.04,2292.57 2934.14,2292.57 2944.59,2303.01 2944.59,2314.57 2948.59,2318.57 2960.59,2318.57 2964.59,2314.57 2964.59,2303.01 2975.03,2292.57 3005.38,2292.57 3015.83,2303.01 3015.83,2316.37 3019.83,2320.37 3030.43,2320.37 3034.43,2316.37 3034.43,2300.81 3044.87,2290.37 3065.98,2290.37 3076.43,2300.81 3076.43,2315.97 3080.43,2319.97 3093.83,2319.97 3096.43,2317.37 3096.43,2300.81 3106.87,2290.37 3141.22,2290.37 3151.66,2300.81 3151.66,2314.57 3155.66,2318.57 3169.06,2318.57 3171.66,2315.97 3171.66,2300.81 3182.11,2290.37 3203.22,2290.37 3213.66,2300.81 3213.66,2315.77 3217.66,2319.77 3231.06,2319.77 3233.66,2317.17 3233.66,2300.81 3244.11,2290.37 3265.22,2290.37 3275.66,2300.81 3275.66,2316.77 3279.66,2320.77 3293.06,2320.77 3295.66,2318.17 3295.66,2300.81 3306.11,2290.37 3327.22,2290.37 3337.66,2300.81 3337.66,2316.97 3341.66,2320.97 3355.06,2320.97 3357.66,2318.37 3357.66,2300.81 3368.11,2290.37 3389.22,2290.37 3399.66,2300.81 3399.66,2315.97 3403.66,2319.97 3417.06,2319.97 3421.06,2315.97 3421.06,2303.01 3431.51,2292.57 3587.96,2292.57 3598.4,2303.01 3598.4,2417.97 3612,2431.57 4840.44,2431.57 cw(c4840.44,2426.97) 4845.04,2426.97 ccw(c4849.64,2426.97) 4849.64,2422.37 4856.44,2422.37 ccw(c4856.44,2426.97) 4861.04,2426.97 cw(c4865.64,2426.97) 4865.64,2431.57 4872.44,2431.57 cw(c4872.44,2426.97) 4877.04,2426.97 ccw(c4881.64,2426.97) 4881.64,2422.37 4888.44,2422.37 ccw(c4888.44,2426.97) 4893.04,2426.97 cw(c4897.64,2426.97) 4897.64,2431.57 4912.76,2431.57 5016.06,2534.87 5068.5,2534.87 v1(5075,2528.37)
  BOTTOM w4.2: J19.21@4980.62,2529.31 5012.04,2529.31 5017.28,2534.55 5068.82,2534.55 v1(5075,2528.37)
MIPI_DPHY0_TX_D1P: J4.45 J19.20 | length 4930.8
  TOP w4.2: v1(1174,2249.37) 1174,2265.02 1181.4,2272.42 1181.4,2339.41 1282.28,2440.29 1282.28,2517.7 1280.01,2519.97 J4.45@1280.01,2543.51
  ART03 w4: v1(1174,2249.37) 1181,2256.37 1181,2320.93 1196.44,2336.37 2721.8,2336.37 2754.6,2303.57 2929.59,2303.57 2933.59,2307.57 2933.59,2319.13 2944.03,2329.57 2965.14,2329.57 2975.59,2319.13 2975.59,2307.57 2979.59,2303.57 3000.83,2303.57 3004.83,2307.57 3004.83,2320.93 3015.27,2331.37 3034.98,2331.37 3045.43,2320.93 3045.43,2305.37 3049.43,2301.37 3061.43,2301.37 3065.43,2305.37 3065.43,2320.53 3075.87,2330.97 3098.38,2330.97 3107.43,2321.93 3107.43,2305.37 3111.43,2301.37 3136.66,2301.37 3140.66,2305.37 3140.66,2319.13 3151.11,2329.57 3173.62,2329.57 3182.66,2320.53 3182.66,2305.37 3186.66,2301.37 3198.66,2301.37 3202.66,2305.37 3202.66,2320.33 3213.11,2330.77 3235.62,2330.77 3244.66,2321.73 3244.66,2305.37 3248.66,2301.37 3260.66,2301.37 3264.66,2305.37 3264.66,2321.33 3275.11,2331.77 3297.62,2331.77 3306.66,2322.73 3306.66,2305.37 3310.66,2301.37 3322.66,2301.37 3326.66,2305.37 3326.66,2321.53 3337.11,2331.97 3359.62,2331.97 3368.66,2322.93 3368.66,2305.37 3372.66,2301.37 3384.66,2301.37 3388.66,2305.37 3388.66,2320.53 3399.11,2330.97 3421.62,2330.97 3432.06,2320.53 3432.06,2307.57 3436.06,2303.57 3583.4,2303.57 3587.4,2307.57 3587.4,2422.53 3607.44,2442.57 4908.2,2442.57 5011.5,2545.87 5066.5,2545.87 v1(5075,2554.37)
  BOTTOM w4.2: J19.20@4980.62,2548.99 5012.04,2548.99 5015.28,2545.75 5066.38,2545.75 v1(5075,2554.37)
MIPI_DPHY0_TX_D2N: J4.35 J19.18 | length 4930.2
  TOP w4.2: v1(1081,2249.37) 1081,2265.02 1073.6,2272.42 1073.6,2317.97 1198.99,2443.36 1198.99,2517.7 1201.27,2519.97 J4.35@1201.27,2543.51
  ART03 w4: v1(1081,2249.37) 1075,2255.37 1075,2370.77 1079.8,2375.57 1092,2375.57 1096,2371.57 1096,2314.01 1106.44,2303.57 1127.56,2303.57 1138,2314.01 1138,2371.57 1142,2375.57 1812.36,2375.57 1841.56,2404.77 1961.44,2404.77 1985.64,2380.57 2725.44,2380.57 2757.84,2348.17 3451.04,2348.17 3462.84,2336.37 3543.8,2336.37 3561.6,2354.17 3561.6,2456.57 3579.4,2474.37 3780.16,2474.37 3799.16,2493.37 4824.4,2493.37 cw(c4824.4,2489.37) 4828.4,2489.37 ccw(c4832.4,2489.37) 4832.4,2485.37 4840.4,2485.37 ccw(c4840.4,2489.37) 4844.4,2489.37 cw(c4848.4,2489.37) 4848.4,2493.37 4856.4,2493.37 cw(c4856.4,2489.37) 4860.4,2489.37 ccw(c4864.4,2489.37) 4864.4,2485.37 4872.4,2485.37 ccw(c4872.4,2489.37) 4876.4,2489.37 cw(c4880.4,2489.37) 4880.4,2493.37 4917.78,2493.37 5017.12,2592.7 5067.5,2592.7 v1(5075,2585.2)
  BOTTOM w4.2: J19.18@4980.62,2588.36 5012.04,2588.36 5016.28,2592.6 5067.6,2592.6 v1(5075,2585.2)
MIPI_DPHY0_TX_D2P: J4.33 J19.17 | length 4931.4
  TOP w4.2: v1(1055,2249.37) 1055,2265.02 1062.4,2272.42 1062.4,2322.61 1187.79,2448 1187.79,2517.7 1185.52,2519.97 J4.33@1185.52,2543.51
  ART03 w4: v1(1055,2249.37) 1064,2258.37 1064,2375.33 1075.24,2386.57 1096.56,2386.57 1107,2376.13 1107,2318.57 1111,2314.57 1123,2314.57 1127,2318.57 1127,2376.13 1137.44,2386.57 1807.8,2386.57 1837,2415.77 1966,2415.77 1990.2,2391.57 2730,2391.57 2762.4,2359.17 3455.6,2359.17 3467.4,2347.37 3539.24,2347.37 3550.6,2358.73 3550.6,2461.13 3574.84,2485.37 3775.6,2485.37 3794.6,2504.37 4913.23,2504.37 5012.56,2603.7 5067.5,2603.7 v1(5075,2611.2)
  BOTTOM w4.2: J19.17@4980.62,2608.05 5012.04,2608.05 5016.28,2603.8 5067.6,2603.8 v1(5075,2611.2)
MIPI_DPHY0_TX_D3N: J4.31 J19.30 | length 4928.2
  TOP w4.2: v1(1051,2124.37) 1051,2140.02 1043.6,2147.42 1043.6,2215.77 1022,2237.37 1022,2308.37 1169.77,2456.14 J4.31@1169.77,2543.51
  ART03 w4: v1(1051,2124.37) 1043.4,2131.97 1043.4,2144.37 1047.4,2148.37 1077.44,2148.37 1112.84,2112.97 1592.6,2112.97 1634.2,2154.57 1634.2,2184.41 1649.16,2199.37 2368,2199.37 2425.4,2141.97 2752.96,2141.97 2774.36,2163.37 3427,2163.37 3450,2140.37 3713.8,2140.37 3734,2160.57 3734,2263.17 3745.4,2274.57 4237.6,2274.57 4257.4,2294.37 4634.61,2294.37 cw(c4634.61,2290.37) 4638.61,2290.37 ccw(c4642.61,2290.37) 4642.61,2286.37 4650.61,2286.37 ccw(c4650.61,2290.37) 4654.61,2290.37 cw(c4658.61,2290.37) 4658.61,2294.37 4666.61,2294.37 cw(c4666.61,2290.37) 4670.61,2290.37 ccw(c4674.61,2290.37) 4674.61,2286.37 4682.61,2286.37 ccw(c4682.61,2290.37) 4686.61,2290.37 cw(c4690.61,2290.37) 4690.61,2294.37 4950.56,2294.37 5011.14,2354.95 5067.5,2354.95 v1(5075,2347.45)
  BOTTOM w4.2: J19.30@4980.62,2352.14 5012.04,2352.14 5015.29,2355.39 5067.07,2355.39 v1(5075,2347.45)
MIPI_DPHY0_TX_D3P: J4.29 J19.29 | length 4930.4
  TOP w4.2: v1(1025,2124.37) 1025,2140.02 1032.4,2147.42 1032.4,2211.13 1010.8,2232.73 1010.8,2313.01 1158.57,2460.78 1158.57,2515.42 1154.02,2519.97 J4.29@1154.02,2543.51
  ART03 w4: v1(1025,2124.37) 1032.4,2131.77 1032.4,2148.93 1042.84,2159.37 1082,2159.37 1117.4,2123.97 1588.04,2123.97 1623.2,2159.13 1623.2,2188.97 1644.6,2210.37 2372.56,2210.37 2429.96,2152.97 2748.4,2152.97 2769.8,2174.37 3431.56,2174.37 3454.56,2151.37 3709.24,2151.37 3723,2165.13 3723,2267.73 3740.84,2285.57 4233.04,2285.57 4252.84,2305.37 4946,2305.37 5006.59,2365.95 5067.5,2365.95 v1(5075,2373.45)
  BOTTOM w4.2: J19.29@4980.62,2371.83 5012.04,2371.83 5017.29,2366.59 5068.13,2366.59 v1(5075,2373.45)
MIPI_DPHY1_RX_CLKN: J4.87 J22.10 | length 4927.3
  TOP w4.2: v1(1416.2,1799.37) 1408.2,1807.37 1408.2,1821.1 cw(c1413,1821.1) 1413,1825.9 ccw(c1413,1830.7) 1417.8,1830.7 1417.8,1837.9 ccw(c1413,1837.9) 1413,1842.7 cw(c1413,1847.5) 1408.2,1847.5 1408.2,2327.57 1477.8,2397.17 1537.8,2397.17 1608.44,2467.81 1608.44,2517.7 1610.72,2519.97 J4.87@1610.72,2543.51 ; v1(4903.86,1704.79) 4897.6,1711.06 4897.6,1761.67 4906,1770.07 4918.46,1770.07 4946.41,1742.12 J22.10@4978.61,1742.12
  ART03 w4: v1(1416.2,1799.37) 1404.62,1810.95 1404.62,1852.63 1416.36,1864.37 1862.36,1864.37 1881.36,1883.37 2897.64,1883.37 2983.04,1797.97 4347.99,1797.97 4351.99,1793.97 4351.99,1771.81 4362.43,1761.37 4383.54,1761.37 4393.99,1771.81 4393.99,1793.97 4397.99,1797.97 4409.99,1797.97 4413.99,1793.97 4413.99,1771.21 4424.43,1760.77 4445.54,1760.77 4455.99,1771.21 4455.99,1793.97 4459.99,1797.97 4471.99,1797.97 4475.99,1793.97 4475.99,1768.61 4486.43,1758.17 4507.54,1758.17 4517.99,1768.61 4517.99,1793.97 4521.99,1797.97 4555.39,1797.97 4710.99,1642.37 4879.2,1642.37 4895.96,1659.13 4895.96,1696.89 v1(4903.86,1704.79)
MIPI_DPHY1_RX_CLKP: J4.85 J22.9 | length 4929.4
  TOP w4.2: v1(1390.2,1799.37) 1397,1806.17 1397,2332.21 1473.16,2408.37 1533.16,2408.37 1597.24,2472.45 1597.24,2517.7 1594.97,2519.97 J4.85@1594.97,2543.51 ; v1(4877.86,1704.79) 4880,1706.93 4882.2,1706.93 4886.4,1711.13 4886.4,1766.31 4901.36,1781.27 4923.1,1781.27 4942.56,1761.81 J22.9@4978.61,1761.81
  ART03 w4: v1(1390.2,1799.37) 1393.62,1802.79 1393.62,1857.19 1411.8,1875.37 1857.8,1875.37 1876.8,1894.37 2902.2,1894.37 2987.6,1808.97 4352.54,1808.97 4362.99,1798.53 4362.99,1776.37 4366.99,1772.37 4378.99,1772.37 4382.99,1776.37 4382.99,1798.53 4393.43,1808.97 4414.54,1808.97 4424.99,1798.53 4424.99,1775.77 4428.99,1771.77 4440.99,1771.77 4444.99,1775.77 4444.99,1798.53 4455.43,1808.97 4476.54,1808.97 4486.99,1798.53 4486.99,1773.17 4490.99,1769.17 4502.99,1769.17 4506.99,1773.17 4506.99,1798.53 4517.43,1808.97 4559.94,1808.97 4715.54,1653.37 4874.64,1653.37 4884.96,1663.69 4884.96,1697.69 v1(4877.86,1704.79)
MIPI_DPHY1_RX_D0N: J4.95 J22.12 | length 4931.9
  TOP w4.2: v1(1556.2,1799.37) 1548,1807.57 1548,1827.59 cw(c1554,1827.59) 1554,1833.59 ccw(c1554,1839.59) 1560,1839.59 1560,1844.39 ccw(c1554,1844.39) 1554,1850.39 cw(c1554,1856.39) 1548,1856.39 1548,1888.37 1508.2,1928.17 1508.2,2038 cw(c1512.9,2038) 1512.9,2042.7 ccw(c1512.9,2047.4) 1517.6,2047.4 1517.6,2054.8 ccw(c1512.9,2054.8) 1512.9,2059.5 cw(c1512.9,2064.2) 1508.2,2064.2 1508.2,2071.6 cw(c1512.9,2071.6) 1512.9,2076.3 ccw(c1512.9,2081) 1517.6,2081 1517.6,2088.4 ccw(c1512.9,2088.4) 1512.9,2093.1 cw(c1512.9,2097.8) 1508.2,2097.8 1508.2,2105.2 cw(c1512.9,2105.2) 1512.9,2109.9 ccw(c1512.9,2114.6) 1517.6,2114.6 1517.6,2122 ccw(c1512.9,2122) 1512.9,2126.7 cw(c1512.9,2131.4) 1508.2,2131.4 1508.2,2138.8 cw(c1512.9,2138.8) 1512.9,2143.5 ccw(c1512.9,2148.2) 1517.6,2148.2 1517.6,2155.6 ccw(c1512.9,2155.6) 1512.9,2160.3 cw(c1512.9,2165) 1508.2,2165 1508.2,2313.53 1534.04,2339.37 1570,2339.37 1671.43,2440.8 1671.43,2517.7 1673.71,2519.97 J4.95@1673.71,2543.51 ; J22.12@4978.61,1702.75 5008.38,1702.75 5012.4,1706.77 5036.4,1706.77 5044.8,1698.37 5044.8,1657.18 v1(5037.4,1649.78)
  ART03 w4: v1(1556.2,1799.37) 1546.7,1789.87 1546.7,1783.37 1552.7,1777.37 1676.44,1777.37 1708.44,1809.37 2851.6,1809.37 2923.6,1737.37 4005.6,1737.37 4017.4,1725.57 4017.4,1703.37 4021.4,1699.37 4046.96,1699.37 4050.96,1703.37 4050.96,1731.13 4061.41,1741.57 4082.52,1741.57 4092.96,1731.13 4092.96,1703.37 4096.96,1699.37 4108.96,1699.37 4112.96,1703.37 4112.96,1733.13 4123.41,1743.57 4144.52,1743.57 4154.96,1733.13 4154.96,1703.37 4158.96,1699.37 4170.96,1699.37 4174.96,1703.37 4174.96,1734.93 4185.41,1745.37 4206.52,1745.37 4216.96,1734.93 4216.96,1703.37 4220.96,1699.37 4588.4,1699.37 4698.4,1589.37 5018.04,1589.37 5043.5,1614.82 5043.5,1643.69 v1(5037.4,1649.78)
MIPI_DPHY1_RX_D0P: J4.93 J22.11 | length 4929.3
  TOP w4.2: v1(1530.2,1799.37) 1536.8,1805.97 1536.8,1883.73 1497,1923.53 1497,2318.17 1529.4,2350.57 1565.36,2350.57 1660.23,2445.44 1660.23,2517.7 1657.96,2519.97 J4.93@1657.96,2543.51 ; J22.11@4978.61,1722.44 5006.73,1722.44 5011.2,1717.97 5041.04,1717.97 5056,1703.01 5056,1657.18 v1(5063.4,1649.78)
  ART03 w4: v1(1530.2,1799.37) 1535.7,1793.87 1535.7,1778.81 1548.14,1766.37 1681,1766.37 1713,1798.37 2847.04,1798.37 2919.04,1726.37 4001.04,1726.37 4006.4,1721.01 4006.4,1698.81 4016.84,1688.37 4051.52,1688.37 4061.96,1698.81 4061.96,1726.57 4065.96,1730.57 4077.96,1730.57 4081.96,1726.57 4081.96,1698.81 4092.41,1688.37 4113.52,1688.37 4123.96,1698.81 4123.96,1728.57 4127.96,1732.57 4139.96,1732.57 4143.96,1728.57 4143.96,1698.81 4154.41,1688.37 4175.52,1688.37 4185.96,1698.81 4185.96,1730.37 4189.96,1734.37 4201.96,1734.37 4205.96,1730.37 4205.96,1698.81 4216.41,1688.37 4583.84,1688.37 4693.84,1578.37 5022.6,1578.37 5054.5,1610.27 5054.5,1640.88 v1(5063.4,1649.78)
MIPI_DPHY1_RX_D1N: J4.91 J22.8 | length 4929.1
  TOP w4.2: v1(1485,1826.77) 1478.6,1820.37 1464.2,1820.37 1460,1824.57 1460,1844.37 cw(c1465.1,1844.37) 1465.1,1849.47 ccw(c1465.1,1854.57) 1470.2,1854.57 1470.2,1861.17 ccw(c1465.1,1861.17) 1465.1,1866.27 cw(c1465.1,1871.37) 1460,1871.37 1460,1906.31 cw(c1464.9,1906.31) 1464.9,1911.21 ccw(c1464.9,1916.11) 1469.8,1916.11 1469.8,1923.11 ccw(c1464.9,1923.11) 1464.9,1928.01 cw(c1464.9,1932.91) 1460,1932.91 1460,1939.91 cw(c1464.9,1939.91) 1464.9,1944.81 ccw(c1464.9,1949.71) 1469.8,1949.71 1469.8,1956.71 ccw(c1464.9,1956.71) 1464.9,1961.61 cw(c1464.9,1966.51) 1460,1966.51 1460,1973.51 cw(c1464.9,1973.51) 1464.9,1978.41 ccw(c1464.9,1983.31) 1469.8,1983.31 1469.8,1990.31 ccw(c1464.9,1990.31) 1464.9,1995.21 cw(c1464.9,2000.11) 1460,2000.11 1460,2007.11 cw(c1464.9,2007.11) 1464.9,2012.01 ccw(c1464.9,2016.91) 1469.8,2016.91 1469.8,2023.91 ccw(c1464.9,2023.91) 1464.9,2028.81 cw(c1464.9,2033.71) 1460,2033.71 1460,2316.77 1513,2369.77 1560.4,2369.77 1639.94,2449.31 1639.94,2517.7 1642.21,2519.97 J4.91@1642.21,2543.51 ; J22.8@4978.61,1781.49 4979.55,1782.43 5036.49,1782.43 v1(5046.59,1772.34)
  ART03 w4: v1(1485,1826.77) 1493.4,1818.37 1504,1818.37 1525,1839.37 2896,1839.37 2963,1772.37 4241.4,1772.37 4253.6,1760.17 4253.6,1740.97 4259.2,1735.37 4283.12,1735.37 4287.12,1739.37 4287.12,1765.73 4297.57,1776.17 4318.68,1776.17 4329.12,1765.73 4329.12,1739.37 4333.12,1735.37 4593.6,1735.37 4708.6,1620.37 4923,1620.37 4931,1628.37 4931,1659.93 4945.44,1674.37 4990.2,1674.37 4994.2,1678.37 4994.2,1690.37 4990.2,1694.37 4970.04,1694.37 4957.6,1706.81 4957.6,1730.13 4970.84,1743.37 5008.33,1743.37 ccw(c5008.33,1747.87) 5012.83,1747.87 cw(c5017.33,1747.87) 5017.33,1752.37 5024.33,1752.37 cw(c5024.33,1747.87) 5028.83,1747.87 ccw(c5033.33,1747.87) 5033.33,1743.37 5046.24,1743.37 5053.59,1750.71 5053.59,1765.34 v1(5046.59,1772.34)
